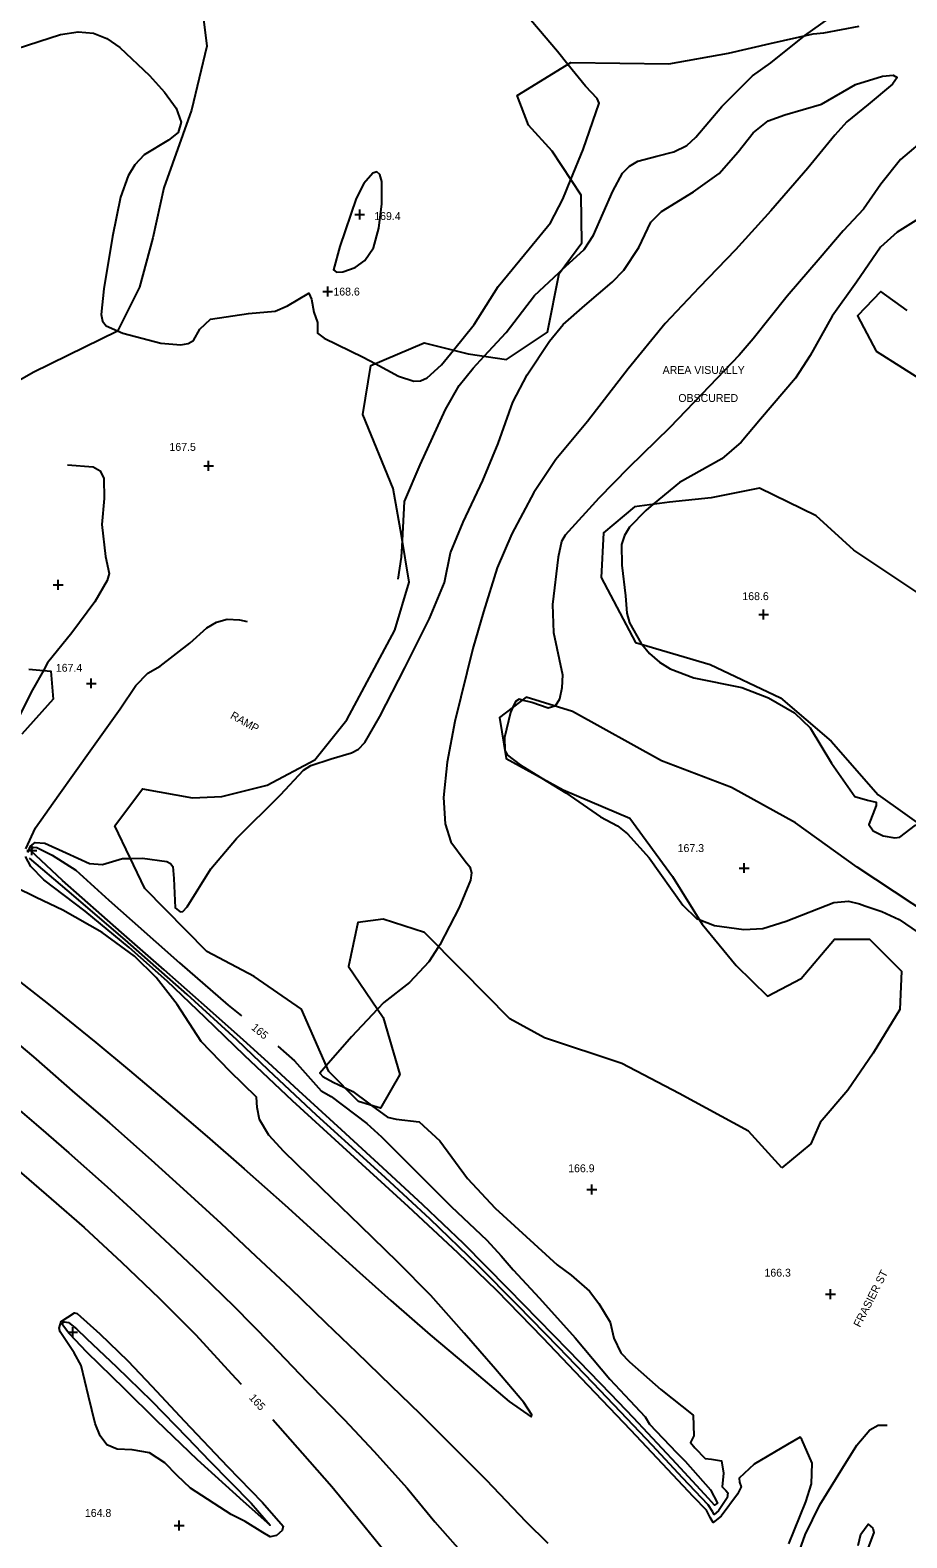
# Model space of a CAD drawing. Extents: x 1467615 to 2003689, y 770235 to 1108726.
# Drawn here: x 1999039.9 to 1999262.1, y 775241.1 to 775623.3 of the extents above; entities that cross this region are included whole.
import ezdxf

# ---------------------------------------------------------------- set-up
doc = ezdxf.new("R2010")
doc.units = 0
for name, color, linetype in [('RD_DTM_Major1', 7, 'Continuous'), ('RD_DTM_Major1_Lbl', 7, 'Continuous'), ('RD_DTM_Minor1', 7, 'Continuous'), ('RD_DTM_Minor2', 7, 'Continuous'), ('RD_DTM_Obscure', 7, 'Continuous'), ('RD_DTM_Spot_Elev', 7, 'Continuous'), ('RD_TX_Misc1', 7, 'Continuous')]:
    doc.layers.add(name, color=color, linetype=linetype)

msp = doc.modelspace()

# ---------------------------------------------------------------- linework, layer by layer
at = {"layer": 'RD_DTM_Major1'}
for points in [[(1999102.66, 775365.75), (1999106.92, 775361.99), (1999113.65, 775354.41), (1999116.16, 775353.02), (1999125.2, 775346.17), (1999128.92, 775342.77), (1999138.24, 775333.49), (1999146.62, 775325.09), (1999155.61, 775316.58), (1999159.3, 775312.55), (1999162.31, 775309.07), (1999168.96, 775301.86), (1999178, 775291.76), (1999186.86, 775281.29), (1999191.91, 775275.87), (1999195.82, 775271.73), (1999196.88, 775269.88), (1999203.76, 775262.69), (1999205.89, 775260.49), (1999212.34, 775253.23), (1999214.14, 775249.84), (1999213.36, 775249.41), (1999211.83, 775251.1), (1999203.69, 775259.84), (1999192.81, 775271.55), (1999187.11, 775277.47), (1999176.32, 775288.57), (1999161.12, 775304.16), (1999149.74, 775315.72), (1999139.45, 775325.51), (1999129.26, 775334.87), (1999118.77, 775344.49), (1999108, 775354.38), (1999100.22, 775361.59), (1999093.91, 775367.25), (1999084.7, 775375.45), (1999073.84, 775385.06), (1999063.04, 775394.58), (1999048.02, 775407.76), (1999039.91, 775415.36), (1999040.61, 775416.16), (1999041.55, 775416.1), (1999045.41, 775414.19), (1999051.46, 775410.36), (1999059.79, 775402.75), (1999065.68, 775397.49), (1999077.73, 775386.91), (1999090.08, 775376.15), (1999093.41, 775373.39)], [(1999036.38, 775334.67), (1999045.22, 775327.07), (1999053.52, 775319.8), (1999062.98, 775310.99), (1999072.56, 775301.89), (1999081.89, 775292.57), (1999090.93, 775282.65), (1999093.34, 775280.02)], [(1999101.38, 775271.12), (1999108.93, 775262.54), (1999116.36, 775254.06), (1999123.68, 775245.18), (1999132.48, 775234.35)], [(1999249.83, 775239.12), (1999250.44, 775242.02), (1999252.36, 775244.53), (1999253.47, 775243.57), (1999253.74, 775242.42), (1999252.29, 775238.64)]]:
    msp.add_lwpolyline(points, dxfattribs=at)
at = {"layer": 'RD_DTM_Minor1'}
for points in [[(1999176.17, 775614.65), (1999173.54, 775617.89), (1999163.93, 775629.28), (1999162.66, 775631.24), (1999158.99, 775641.48), (1999155.71, 775647.49), (1999154.14, 775650.63), (1999154.06, 775653.1), (1999157.16, 775661.91), (1999157.48, 775667.98), (1999157.06, 775670.59), (1999156.07, 775672.09), (1999154.44, 775672.06), (1999150.26, 775669.33), (1999146.96, 775667.16)], [(1999236.21, 775621.92), (1999236.23, 775621.94), (1999247.87, 775630.2), (1999257.16, 775636.77)], [(1999124.45, 775584.49), (1999122.52, 775580.61), (1999118.34, 775568.48), (1999116.75, 775562.53), (1999117.52, 775561.98), (1999119.14, 775562.02), (1999122.27, 775563.13), (1999124.74, 775564.89), (1999126.88, 775568.18), (1999128.29, 775573.11), (1999129.05, 775579.27), (1999129.01, 775584.97), (1999128.55, 775586.74), (1999127.75, 775587.4), (1999126.72, 775587.08), (1999124.45, 775584.49)], [(1999147.15, 775542.21), (1999152.44, 775548.69), (1999158.53, 775558.35), (1999166.38, 775567.87), (1999171.75, 775574.44), (1999174.9, 775580.47), (1999176.96, 775585.51)], [(1999154.99, 775540.66), (1999160.58, 775546.69), (1999167.72, 775556.1), (1999173.88, 775561.84), (1999174.7, 775562.58)], [(1999062.01, 775547.08), (1999063.39, 775546.47), (1999073, 775543.96), (1999078.06, 775543.51), (1999079.9, 775543.86), (1999081.29, 775544.67), (1999082.86, 775547.51), (1999085.54, 775550.05), (1999095.22, 775551.5), (1999102.01, 775552.06), (1999105.11, 775553.42), (1999110.53, 775556.63), (1999111.16, 775555.09), (1999111.79, 775551.8), (1999112.67, 775549.18), (1999112.67, 775546.55), (1999114.4, 775545.21), (1999124.33, 775540.39), (1999127.34, 775538.78)], [(1999049.32, 775513.11), (1999055.81, 775512.65), (1999057.58, 775511.61), (1999058.51, 775509.68), (1999058.6, 775504.63), (1999058.03, 775498.04), (1999058.96, 775489.91), (1999059.87, 775485.61), (1999059.34, 775483.77), (1999056.24, 775478.42), (1999050.4, 775470.57), (1999044.29, 775462.95), (1999043.21, 775461.02)], [(1999197.82, 775503.13), (1999195.96, 775501.58), (1999191.84, 775497.33), (1999190.51, 775495.21), (1999189.76, 775492.92), (1999189.84, 775487.65), (1999190.78, 775479.94), (1999191.15, 775475.48), (1999191.8, 775473.11), (1999194.74, 775467.86), (1999194.94, 775467.62)], [(1999133.16, 775484.1), (1999134, 775489.7), (1999134.23, 775493.92)], [(1999038.73, 775415.76), (1999041.22, 775421.07), (1999047.14, 775429.5), (1999055.03, 775440.6), (1999062.71, 775451.24), (1999066.64, 775457.2), (1999069.68, 775460.29), (1999072.81, 775462.07), (1999080.36, 775467.93), (1999084.69, 775471.79), (1999087.08, 775473.24), (1999089.81, 775473.99), (1999092.94, 775473.85), (1999094.91, 775473.44)], [(1999172.96, 775451.97), (1999172.92, 775451.91), (1999171.2, 775451.44), (1999167.05, 775452.85), (1999164.6, 775453.49)], [(1999162.23, 775451.7), (1999161.61, 775450.36), (1999160.09, 775443.99), (1999160.19, 775440.66), (1999160.89, 775439.49), (1999164.09, 775437.1), (1999169.59, 775433.7)], [(1999039.27, 775414.86), (1999039.91, 775416.41), (1999041.16, 775417.37), (1999043.55, 775417.22), (1999048.97, 775414.78), (1999054.88, 775412.03), (1999058.16, 775411.81), (1999063.27, 775413.28), (1999065.3, 775413.34)], [(1999232.19, 775239.6), (1999236.55, 775250.2), (1999237.93, 775254.74), (1999238.15, 775260), (1999235.53, 775266.03), (1999235.08, 775266.6), (1999231.9, 775264.76), (1999223.4, 775259.8), (1999219.65, 775256.22), (1999219.68, 775255.17), (1999220.11, 775254.04), (1999219.16, 775252.19), (1999215.04, 775246.55), (1999213.01, 775244.97), (1999212.23, 775246.23), (1999211.37, 775248.12), (1999208.02, 775251.48), (1999200.18, 775259.82), (1999192.14, 775268.36), (1999181.33, 775279.74), (1999169.8, 775291.79), (1999158.27, 775303.72), (1999148.26, 775313.37), (1999135.8, 775324.99), (1999127.95, 775332.22), (1999119.15, 775340.18), (1999106.33, 775351.89), (1999094.22, 775363.34), (1999084.26, 775373.04), (1999074.56, 775382.19), (1999064.92, 775390.77), (1999053.84, 775399.93), (1999043.36, 775407.91), (1999040.04, 775411.27), (1999038.7, 775413.84)], [(1999126.42, 775350.7), (1999130.47, 775347.73), (1999132.65, 775347.27), (1999138.48, 775346.59), (1999143.73, 775341.78), (1999150.73, 775332.15), (1999157.73, 775324.71), (1999173.49, 775310.28), (1999176.99, 775307.65), (1999181.65, 775303.61), (1999184.01, 775300.52), (1999186.91, 775295.76), (1999187.86, 775291.68), (1999189.65, 775288.03), (1999191.79, 775285.71), (1999199.77, 775278.67), (1999207.96, 775272.2), (1999208.12, 775266.92), (1999207.32, 775265.27), (1999208.37, 775263.89), (1999211.04, 775261.2), (1999212.62, 775260.99), (1999215.1, 775260.61), (1999215.66, 775257.44), (1999215.33, 775254.02), (1999216.22, 775253.05), (1999216.73, 775252.51), (1999216.56, 775251.23), (1999214.4, 775247.94), (1999213.26, 775247.04), (1999212.82, 775247.75), (1999211.76, 775249.48), (1999205.26, 775256.27), (1999197.63, 775264.47), (1999189.57, 775273.02), (1999182.6, 775280.33), (1999173.84, 775289.41), (1999163.51, 775300.03), (1999153.39, 775310.25), (1999141.3, 775321.85), (1999129.94, 775332.33), (1999121.53, 775340.01), (1999112.45, 775348.27), (1999100.29, 775359.63), (1999092.24, 775367.31), (1999079.63, 775378.82), (1999063.98, 775392.68), (1999049.24, 775405.3), (1999039.72, 775413.43)], [(1999035.13, 775383.77), (1999044.5, 775376.35), (1999056.51, 775366.63), (1999065.02, 775359.55), (1999074.86, 775351.28), (1999084.76, 775342.84), (1999094.11, 775334.65), (1999104.46, 775325.54), (1999113.66, 775317.18), (1999123.35, 775308.34), (1999131.33, 775301.24), (1999141.28, 775292.52), (1999150.7, 775284.58), (1999161.34, 775275.62), (1999166.9, 775271.8), (1999167.05, 775272.28), (1999165.01, 775275.42), (1999157.87, 775283.82), (1999149.9, 775292.99), (1999141.47, 775302.49), (1999133.11, 775310.94), (1999123.61, 775320.15), (1999113.8, 775329.66), (1999104.14, 775339.02), (1999100.36, 775343.18), (1999097.97, 775347.19), (1999097.4, 775350.21), (1999097.22, 775352.84), (1999090.5, 775359.44), (1999083.24, 775366.92), (1999077.12, 775376.29), (1999071.84, 775383.19), (1999066.3, 775388.55), (1999058.1, 775394.56), (1999048.17, 775400.26), (1999041.39, 775403.39), (1999036.07, 775406.06)], [(1999209.49, 775397.85), (1999213.39, 775396.34), (1999220.83, 775395.33), (1999225.66, 775395.61), (1999231.54, 775397.46), (1999243.66, 775402.17), (1999247.3, 775402.53), (1999250.17, 775401.85), (1999251.45, 775401.3), (1999255.8, 775399.92), (1999260.15, 775397.82), (1999265.04, 775394.58)], [(1999143.41, 775390.94), (1999140.97, 775387.16), (1999136.06, 775381.86), (1999129.51, 775376.84), (1999127.92, 775375.15)], [(1999031.56, 775370.6), (1999040.71, 775363), (1999051.19, 775353.85), (1999059.98, 775346.27), (1999070.55, 775336.88), (1999078.64, 775329.55), (1999088.16, 775320.87), (1999097.07, 775312.51), (1999105.74, 775304.35), (1999114.81, 775295.6), (1999122.57, 775288.2), (1999131.43, 775279.6), (1999138.62, 775272.65), (1999147.6, 775263.63), (1999155.49, 775255.75), (1999165.5, 775245.22), (1999171.15, 775239.7)], [(1999114.94, 775360.78), (1999113.28, 775358.88), (1999114.06, 775358.02), (1999116.7, 775356.59), (1999119.59, 775355.23)], [(1999031.83, 775353.97), (1999042.54, 775344.87), (1999049.7, 775338.66), (1999059.38, 775330.06), (1999066.37, 775323.66), (1999075.31, 775315.4), (1999083.08, 775308.02), (1999091.6, 775299.72), (1999100.78, 775290.36), (1999110.11, 775280.65), (1999119.52, 775270.99), (1999126.99, 775263.1), (1999135.43, 775253.64), (1999142.5, 775245.14), (1999150.82, 775235.71)], [(1999057.56, 775292.8), (1999064.62, 775285.96), (1999070.68, 775279.56), (1999079.01, 775270.7), (1999089.92, 775259.18), (1999098.8, 775250.04), (1999104.01, 775244.04), (1999103.72, 775242.94), (1999102.34, 775241.68), (1999100.75, 775241.32), (1999098.88, 775242.46), (1999094.38, 775245.25), (1999090.81, 775246.99), (1999080.5, 775253.67), (1999077.12, 775256.89), (1999074.03, 775260.06), (1999070.1, 775262.67), (1999065.75, 775263.4), (1999061.9, 775263.55), (1999059.31, 775264.7), (1999057.63, 775266.94), (1999056.32, 775270.09), (1999054.64, 775276.97), (1999052.75, 775284.74), (1999051.05, 775288.03), (1999047.44, 775293.29), (1999047.22, 775294.22), (1999047.76, 775295.92), (1999051.1, 775298.17), (1999051.79, 775297.97), (1999057.56, 775292.8)], [(1999054.16, 775291.6), (1999061.74, 775284.46), (1999070.61, 775275.83), (1999079.68, 775266.49), (1999085.33, 775260.64), (1999095.85, 775249.87), (1999100.73, 775244.29), (1999093.97, 775250.33), (1999082.31, 775260.85), (1999071.96, 775270.78), (1999063.77, 775278.89), (1999054.2, 775288.18), (1999049.8, 775292.78), (1999049.07, 775293.73), (1999047.9, 775295.32), (1999048.56, 775295.82), (1999049.61, 775295.72), (1999051.59, 775294.06), (1999054.16, 775291.6)], [(1999246.65, 775210.11), (1999245.52, 775210.2), (1999242.81, 775211.66), (1999238.21, 775215.45), (1999231.76, 775222.17), (1999229.89, 775225.41), (1999228.92, 775229.46), (1999229.55, 775230.98), (1999230.27, 775231.57), (1999233.27, 775233.31), (1999236.39, 775241.81), (1999240.04, 775249.46), (1999245.85, 775258.78), (1999249.48, 775264.56), (1999252.74, 775268.45), (1999254.84, 775269.66), (1999257.13, 775269.62)]]:
    msp.add_lwpolyline(points, dxfattribs=at)
at = {"layer": 'RD_DTM_Minor2'}
for points in [[(1999033.69, 775617.75), (1999047.55, 775622.22), (1999052.07, 775622.94), (1999055.91, 775622.61), (1999059.29, 775621.25), (1999062.57, 775618.93), (1999070.08, 775611.84), (1999073.91, 775607.62), (1999076.86, 775603.52), (1999078.17, 775600.01), (1999077.35, 775597.4), (1999074.97, 775595.41), (1999068.73, 775591.68), (1999066.36, 775589.22), (1999064.69, 775586.43), (1999062.79, 775580.97), (1999060.76, 775570.98), (1999058.51, 775557.78), (1999057.84, 775551.27), (1999058.16, 775549.51), (1999059.12, 775548.35), (1999062.01, 775547.08)], [(1999174.7, 775562.58), (1999180.34, 775567.72), (1999182.73, 775571.38), (1999187.59, 775582.51), (1999190.05, 775587.04), (1999191.78, 775588.87), (1999193.9, 775590.11), (1999198.71, 775591.42), (1999203.08, 775592.49), (1999206.34, 775594.09), (1999208.67, 775596.18), (1999215.22, 775603.96), (1999223, 775611.76), (1999227.63, 775615.05), (1999236.21, 775621.92)], [(1999176.96, 775585.51), (1999180.06, 775593.1), (1999184.11, 775604.84), (1999183.64, 775605.97), (1999180.66, 775609.14), (1999176.17, 775614.65)], [(1999065.3, 775413.34), (1999068.33, 775413.44), (1999074.54, 775412.58), (1999075.48, 775412.06), (1999075.99, 775411.25), (1999076.27, 775408.29), (1999076.6, 775400.85), (1999077.88, 775399.8), (1999078.56, 775399.9), (1999079.63, 775401.06), (1999085.64, 775410.66), (1999092.17, 775418.35), (1999103.29, 775429.45), (1999109.15, 775435.68), (1999111.02, 775436.86), (1999116.19, 775438.55), (1999121.31, 775440.07), (1999123.14, 775441.08), (1999124.69, 775442.69), (1999128.53, 775449.36), (1999134.86, 775461.69), (1999141.07, 775474.17), (1999144.94, 775483.32), (1999146.39, 775490.78), (1999149.65, 775498.62), (1999154.66, 775509.14), (1999158.55, 775518.51), (1999162.25, 775529.05), (1999165.89, 775535.93), (1999171.5, 775544.49), (1999175, 775548.67), (1999180.48, 775553.49), (1999187.38, 775559.41), (1999190.36, 775562.48), (1999194.17, 775568.27), (1999197.21, 775574.61), (1999199.9, 775577.32), (1999208.06, 775582.33), (1999214.53, 775587.03), (1999219.4, 775592.51), (1999223.19, 775597.34), (1999226.95, 775600.3), (1999231.17, 775601.9), (1999240.46, 775604.58), (1999249.08, 775609.52), (1999255.96, 775611.67), (1999258.63, 775611.95), (1999259.66, 775611.32), (1999258.5, 775609.62), (1999252.34, 775604.51), (1999246.89, 775600.06), (1999243.89, 775596.68), (1999237.06, 775588.36), (1999227.65, 775577.53), (1999218.72, 775567.67), (1999209.51, 775558.12), (1999200.89, 775548.99), (1999191.46, 775537.45), (1999181.14, 775524.12), (1999173.11, 775514.52), (1999167.6, 775506.11), (1999162.02, 775495.65), (1999158.23, 775487.03), (1999154.77, 775475.88), (1999152.08, 775466.54), (1999147.52, 775448.03), (1999145.59, 775437.78), (1999144.65, 775428.77), (1999145.08, 775422.11), (1999146.51, 775417.58), (1999150.14, 775412.66), (1999151.3, 775411.18), (1999151.75, 775409.71), (1999151.48, 775407.79), (1999148.66, 775400.93), (1999143.69, 775391.39), (1999143.41, 775390.94)], [(1999267.73, 775596.66), (1999260.49, 775590.52), (1999255.54, 775584.31), (1999251.15, 775577.92), (1999245.96, 775572.44), (1999240.15, 775565.59), (1999231.77, 775555.9), (1999223.17, 775545.03), (1999219.65, 775540.93), (1999212.1, 775533.09), (1999202.07, 775522.57), (1999191.55, 775512.37), (1999184.02, 775504.66), (1999175.52, 775495.33), (1999174.54, 775493.72), (1999173.72, 775489.71), (1999172.31, 775477.72), (1999172.56, 775470.65), (1999174.79, 775459.86), (1999174.67, 775456.58), (1999174.08, 775453.75), (1999172.96, 775451.97)], [(1999266.04, 775576.14), (1999265.12, 775575.52), (1999259.72, 775572.15), (1999255.44, 775568.33), (1999249.4, 775559.41), (1999243.16, 775550.82), (1999237.63, 775540.81), (1999233.89, 775535.08), (1999225.05, 775524.7), (1999220.14, 775518.85), (1999215.19, 775514.68), (1999204.46, 775508.63), (1999197.82, 775503.13)], [(1999127.34, 775538.78), (1999133.22, 775535.61), (1999137.11, 775534.33), (1999138.81, 775534.44), (1999140.51, 775535.19), (1999144.12, 775538.49), (1999147.15, 775542.21)], [(1999134.23, 775493.92), (1999134.77, 775503.87), (1999138.75, 775513.15), (1999145.13, 775527.15), (1999148.67, 775533.28), (1999152.22, 775537.67), (1999154.99, 775540.66)], [(1999194.94, 775467.62), (1999196.9, 775465.32), (1999199.4, 775463.1), (1999202.16, 775461.37), (1999208.13, 775459.13), (1999220.3, 775456.64), (1999227.09, 775454.07), (1999233.63, 775450.24), (1999237.62, 775446.47), (1999243.03, 775437.49), (1999248.91, 775429.06), (1999252.2, 775428.15), (1999254.36, 775427.56), (1999254.37, 775426.72), (1999252.46, 775421.92), (1999253.6, 775420.3), (1999256.13, 775419.09), (1999259.12, 775418.53), (1999260.34, 775418.75), (1999264.33, 775421.74), (1999265.64, 775421.75)], [(1999043.21, 775461.02), (1999040.44, 775456.11), (1999034.18, 775443.7), (1999034.1, 775443.57)], [(1999164.6, 775453.49), (1999163.85, 775453.69), (1999162.9, 775453.13), (1999162.23, 775451.7)], [(1999169.59, 775433.7), (1999175.67, 775429.95), (1999184.48, 775423.87), (1999188.8, 775421.57), (1999191.32, 775419.6), (1999196.81, 775413.52), (1999205.35, 775401.48), (1999208.79, 775398.13), (1999209.49, 775397.85)], [(1999127.92, 775375.15), (1999121.29, 775368.07), (1999114.94, 775360.78)], [(1999119.59, 775355.23), (1999121.7, 775354.22), (1999125.6, 775351.3), (1999126.42, 775350.7)]]:
    msp.add_lwpolyline(points, dxfattribs=at)
at = {"layer": 'RD_DTM_Obscure'}
for points in [[(1999082.28, 775638.57), (1999084.67, 775619.3), (1999080.73, 775603.05), (1999073.72, 775583.34), (1999070.92, 775570.66), (1999067.57, 775558.21), (1999061.99, 775547.04), (1999049.42, 775540.84), (1999040.59, 775536.55), (1999033.68, 775532.53)], [(1999230.46, 775334.86), (1999222, 775344.15), (1999204.38, 775353.78), (1999189.9, 775361.31), (1999170.29, 775367.89), (1999161.49, 775372.7), (1999149.29, 775384.97), (1999139.8, 775394.6), (1999129.38, 775397.98), (1999122.92, 775397.11), (1999120.56, 775385.96), (1999129.38, 775373.02), (1999133.61, 775358.53), (1999128.72, 775350.02), (1999123.08, 775351.68), (1999115.59, 775359.28), (1999108.67, 775375.16), (1999096.63, 775383.4), (1999084.67, 775389.73), (1999068.97, 775405.73), (1999061.29, 775421.64), (1999068.32, 775430.97), (1999080.98, 775428.72), (1999088.44, 775429.05), (1999099.96, 775431.91), (1999112.06, 775438.36), (1999120.18, 775448.48), (1999132.35, 775471.21), (1999135.91, 775483.4), (1999134.02, 775495.22), (1999131.86, 775507.15), (1999124.18, 775525.87), (1999126.23, 775538.3), (1999139.78, 775544.08), (1999150.93, 775541.25), (1999160.64, 775539.83), (1999171.03, 775546.75), (1999173.98, 775561.6), (1999179.75, 775569.44), (1999179.6, 775581.53), (1999172.25, 775592.61), (1999166.17, 775599.23), (1999163.37, 775606.8), (1999176.97, 775615.14), (1999201.75, 775614.76), (1999216.92, 775617.49), (1999227.52, 775619.92), (1999238.41, 775622.43), (1999241.09, 775622.66), (1999250.03, 775624.33)], [(1999262.24, 775552.22), (1999255.54, 775557.09), (1999249.65, 775550.94), (1999254.38, 775541.97), (1999274.4, 775529.25)], [(1999265.18, 775480.53), (1999248.7, 775491.52), (1999239.16, 775500.19), (1999224.76, 775507.24), (1999212.48, 775504.79), (1999201.92, 775503.68), (1999193.06, 775502.48), (1999185.23, 775495.86), (1999184.67, 775484.53), (1999193.37, 775468.08), (1999212.25, 775462.5), (1999230.1, 775454.02), (1999242.95, 775443.05), (1999254.88, 775429.46), (1999268.37, 775419.79)], [(1999039.56, 775461.34), (1999045.08, 775460.85), (1999045.65, 775453.75), (1999037.71, 775444.82)], [(1999272.92, 775395.62), (1999249.54, 775411.11), (1999233.94, 775422.33), (1999217.65, 775431.29), (1999199.9, 775438.05), (1999177.33, 775450.62), (1999165.6, 775454.25), (1999158.82, 775449.11), (1999160.51, 775438.7), (1999175.03, 775430.71), (1999191.9, 775423.53), (1999202.7, 775408.77), (1999210.22, 775396.68), (1999218.88, 775386.15), (1999226.84, 775378.43), (1999235.32, 775382.91), (1999243.82, 775392.84), (1999252.63, 775392.91), (1999260.76, 775384.79), (1999260.39, 775375.05), (1999253.63, 775363.97), (1999247.16, 775354.59), (1999240.19, 775346.39), (1999237.77, 775340.98), (1999230.46, 775334.86)]]:
    msp.add_lwpolyline(points, dxfattribs=at)
at = {"layer": 'RD_DTM_Spot_Elev'}
for p, q in [((1999122.16, 775576.57), (1999124.66, 775576.57)), ((1999123.41, 775575.32), (1999123.41, 775577.82)), ((1999114.04, 775557.05), (1999116.54, 775557.05)), ((1999115.29, 775555.8), (1999115.29, 775558.3)), ((1999085.1, 775511.61), (1999085.1, 775514.11)), ((1999083.85, 775512.86), (1999086.35, 775512.86)), ((1999045.7, 775482.7), (1999048.2, 775482.7)), ((1999046.95, 775481.45), (1999046.95, 775483.95)), ((1999224.57, 775475.19), (1999227.07, 775475.19)), ((1999225.82, 775473.94), (1999225.82, 775476.44)), ((1999054.1, 775457.73), (1999056.6, 775457.73)), ((1999055.35, 775456.48), (1999055.35, 775458.98)), ((1999039.01, 775415.38), (1999041.51, 775415.38)), ((1999040.26, 775414.13), (1999040.26, 775416.63)), ((1999219.64, 775410.91), (1999222.14, 775410.91)), ((1999220.89, 775409.66), (1999220.89, 775412.16)), ((1999182.29, 775328.16), (1999182.29, 775330.66)), ((1999181.04, 775329.41), (1999183.54, 775329.41)), ((1999241.53, 775302.87), (1999244.03, 775302.87)), ((1999242.78, 775301.62), (1999242.78, 775304.12)), ((1999049.39, 775293.23), (1999051.89, 775293.23)), ((1999050.64, 775291.98), (1999050.64, 775294.48)), ((1999077.64, 775242.96), (1999077.64, 775245.46)), ((1999076.39, 775244.21), (1999078.89, 775244.21))]:
    msp.add_line(p, q, dxfattribs=at)

# ---------------------------------------------------------------- texts
at = {"layer": 'RD_DTM_Major1_Lbl'}
for rotation, p in [(320.4637, (1999095.76, 775370.16)), (312.4047, (1999095.21, 775276.48))]:
    msp.add_text('165', height=2, rotation=rotation, dxfattribs=at).set_placement(p)
at = {"layer": 'RD_DTM_Spot_Elev'}
for s, p in [('169.4', (1999127.1, 775575.19)), ('168.6', (1999116.74, 775556.05)), ('167.5', (1999075.18, 775516.67)), ('168.6', (1999220.43, 775478.83)), ('167.4', (1999046.37, 775460.67)), ('167.3', (1999204.02, 775414.96)), ('166.9', (1999176.27, 775333.78)), ('166.3', (1999226.04, 775307.31)), ('164.8', (1999053.74, 775246.4))]:
    msp.add_text(s, height=2, dxfattribs=at).set_placement(p)
at = {"layer": 'RD_TX_Misc1'}
for s, p in [('AREA VISUALLY', (1999200.22, 775536.18)), ('OBSCURED', (1999204.2, 775529.07))]:
    msp.add_text(s, height=2, dxfattribs=at).set_placement(p)
for s, rotation, p in [('RAMP', 330.9454, (1999090.43, 775448.97)), ('FRASIER ST', 62.9562, (1999250.26, 775294.3))]:
    msp.add_text(s, height=2, rotation=rotation, dxfattribs=at).set_placement(p)

doc.saveas('drawing.dxf')
